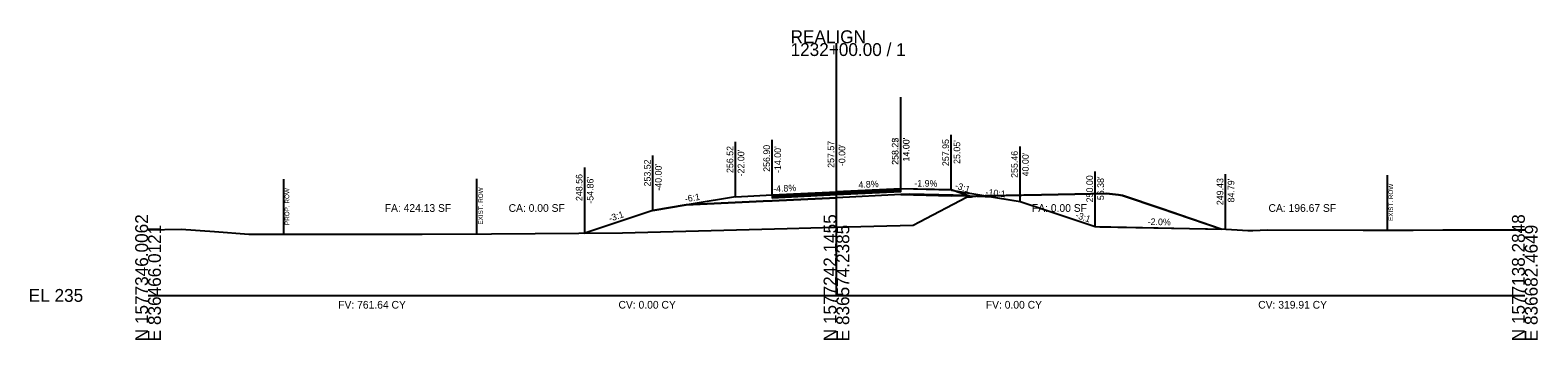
# Model space of a CAD drawing. Extents: x -26 to 6303, y -16 to 9563.
# Drawn here: x 974.3 to 1302.8, y 990.3 to 1057.8 of the extents above; entities that cross this region are included whole.
import ezdxf

# ---------------------------------------------------------------- set-up
doc = ezdxf.new("R2010")
doc.units = 0
for name, color, linetype in [('ASPHALT_19MM1', 7, 'Continuous'), ('ASPHALT_9_5MM1', 7, 'Continuous'), ('CONST_DCH', 7, 'Continuous'), ('CONST_LV3', 7, 'Continuous'), ('Draft_XS_Grid', 7, 'Continuous'), ('DTM_TEMP_DROP', 7, 'Continuous'), ('DTM_X_GROUND', 7, 'Continuous'), ('X_PROFILES_1', 7, 'Continuous'), ('X_TRANS_EOP', 7, 'Continuous'), ('XS_CELL', 7, 'Continuous'), ('XS_M_SHAPES_EARTHWORK', 7, 'Continuous'), ('XS_P_ASPHALT', 7, 'Continuous'), ('XS_P_DR_ASPHALT', 7, 'Continuous'), ('XS_P_GROUND', 7, 'Continuous'), ('XS_P_ROW', 7, 'Continuous'), ('XS_P_SHOULDER', 7, 'Continuous'), ('XS_P_SUBGRADE_GRANULAR', 7, 'Continuous'), ('XS_P_TX_CLEARZONE', 7, 'Continuous'), ('XS_P_TX_FS_BS', 7, 'Continuous'), ('XS_PLAN_CLEAR_ZONE', 7, 'Continuous'), ('XS_SHEET_EW_TX_AREA', 7, 'Continuous'), ('XS_SHEET_EW_TX_VOLUME', 7, 'Continuous'), ('XS_X_ROW', 7, 'Continuous')]:
    doc.layers.add(name, color=color, linetype=linetype)

msp = doc.modelspace()

# ---------------------------------------------------------------- linework, layer by layer
at = {"layer": 'ASPHALT_19MM1'}
msp.add_lwpolyline([(1136, 1021.57), (1136, 1021.3), (1150, 1021.97), (1150, 1021.97), (1164, 1022.64), (1164, 1022.64), (1164, 1022.91), (1164, 1022.91), (1164, 1022.91), (1150, 1022.24), (1150, 1022.24), (1136, 1021.57), (1136, 1021.57)], dxfattribs=at)
at = {"layer": 'ASPHALT_9_5MM1'}
msp.add_lwpolyline([(1136, 1021.9), (1150, 1022.57), (1150, 1022.57), (1164, 1023.25), (1164, 1023.25), (1164, 1023.12), (1164, 1023.12), (1150, 1022.45), (1150, 1022.45), (1136, 1021.78), (1136, 1021.9)], dxfattribs=at)
at = {"layer": 'CONST_LV3'}
for points in [[(1164, 1023.22), (1164, 1023.22), (1150, 1022.57)], [(1175.05, 1022.95), (1175.05, 1022.95), (1164, 1023.22)], [(1110, 1018.52), (1117.29, 1019.73), (1117.29, 1019.73)]]:
    msp.add_lwpolyline(points, dxfattribs=at)
at = {"layer": 'DTM_X_GROUND'}
msp.add_lwpolyline([(1000, 1014.33), (1007.23, 1014.43), (1014.48, 1013.91), (1021.97, 1013.35), (1029.56, 1013.34), (1059.74, 1013.36), (1074.81, 1013.44), (1103.41, 1013.61), (1139.27, 1014.61), (1149.57, 1014.88), (1166.74, 1015.34), (1168.1, 1016.05), (1178.35, 1021.4), (1180.39, 1021.66), (1180.58, 1021.69), (1181.72, 1021.71), (1194.65, 1021.96), (1201.92, 1022.09), (1208.86, 1022.23), (1211.43, 1021.9), (1212.35, 1021.79), (1220.74, 1018.95), (1233.73, 1014.49), (1239.63, 1014.17), (1240.25, 1014.13), (1240.7, 1014.15), (1243.91, 1014.27), (1264.77, 1014.21), (1275.65, 1014.25), (1282.15, 1014.27), (1283, 1014.27), (1300, 1014.29)], dxfattribs=at)
at = {"layer": 'X_TRANS_EOP'}
msp.add_line((1164, 1023.22), (1164, 1043.22), dxfattribs=at)
at = {"layer": 'XS_CELL'}
for p, q in [((1150, 1000), (1150, 1055)), ((1000, 1000), (1150, 1000)), ((1150, 1000), (1300, 1000))]:
    msp.add_line(p, q, dxfattribs=at)
at = {"layer": 'XS_M_SHAPES_EARTHWORK'}
msp.add_lwpolyline([(1095.14, 1013.56), (1103.41, 1013.61), (1139.27, 1014.61), (1149.57, 1014.88), (1166.74, 1015.34), (1168.1, 1016.05), (1178.35, 1021.4), (1179.41, 1021.53), (1178.63, 1021.79), (1166, 1022.07), (1164, 1021.97), (1150, 1021.3), (1136, 1020.63), (1134, 1020.53), (1117.29, 1019.73), (1110, 1018.52)], close=True, dxfattribs=at)
at = {"layer": 'XS_P_GROUND'}
for points in [[(1179.41, 1021.53), (1179.41, 1021.53), (1175, 1023)], [(1175.05, 1022.95), (1190, 1020.46), (1206.38, 1015)], [(1128, 1021.52), (1110, 1018.52), (1095.14, 1013.56)], [(1206.38, 1015), (1207.38, 1014.98)], [(1207.38, 1014.98), (1234.79, 1014.43)]]:
    msp.add_lwpolyline(points, dxfattribs=at)
at = {"layer": 'XS_P_ROW'}
msp.add_line((1029.56, 1013.34), (1029.56, 1025.34), dxfattribs=at)
at = {"layer": 'XS_P_SHOULDER'}
for points in [[(1128, 1021.52), (1136, 1021.9), (1136, 1021.9)], [(1175, 1023), (1164, 1023.25), (1164, 1023.25)], [(1175.05, 1022.95), (1175.05, 1022.95), (1175, 1022.95)]]:
    msp.add_lwpolyline(points, dxfattribs=at)
at = {"layer": 'XS_P_SUBGRADE_GRANULAR'}
for points in [[(1164, 1021.97), (1164, 1021.97), (1150, 1021.3)], [(1164, 1021.97), (1175, 1021.68)], [(1117.29, 1019.73), (1134, 1020.53), (1134, 1020.53), (1136, 1020.63), (1136, 1020.63)], [(1136, 1020.63), (1150, 1021.3), (1150, 1021.3)], [(1184.22, 1021.42), (1184.22, 1021.42), (1177, 1021.71), (1177, 1021.71), (1175, 1021.68)]]:
    msp.add_lwpolyline(points, dxfattribs=at)
at = {"layer": 'XS_P_TX_CLEARZONE'}
for p, q in [((1164, 1023.25), (1164, 1035.25)), ((1164, 1023.22), (1164, 1035.22)), ((1175, 1023), (1175, 1035)), ((1128, 1021.52), (1128, 1033.52)), ((1136, 1021.9), (1136, 1033.9)), ((1150, 1022.57), (1150, 1034.57)), ((1190, 1020.46), (1190, 1032.46)), ((1110, 1018.52), (1110, 1030.52)), ((1095.14, 1013.56), (1095.14, 1027.88)), ((1206.38, 1015), (1206.38, 1027)), ((1234.79, 1014.43), (1234.79, 1026.43))]:
    msp.add_line(p, q, dxfattribs=at)
at = {"layer": 'XS_P_TX_FS_BS'}
for p, q in [((1190, 1020.46), (1206.38, 1015)), ((1206.38, 1015), (1233.84, 1014.45))]:
    msp.add_line(p, q, dxfattribs=at)
for points in [[(1183.14, 1021.74), (1182.42, 1021.72), (1190, 1020.46)], [(1233.84, 1014.45), (1220.74, 1018.95), (1212.35, 1021.79), (1211.43, 1021.9), (1208.86, 1022.23), (1201.92, 1022.09), (1194.65, 1021.96), (1183.14, 1021.74)]]:
    msp.add_lwpolyline(points, dxfattribs=at)
at = {"layer": 'XS_PLAN_CLEAR_ZONE'}
msp.add_lwpolyline([(1136, 1021.78), (1136, 1021.57), (1150, 1022.24), (1150, 1022.24), (1164, 1022.91), (1164, 1022.91), (1164, 1023.12), (1164, 1023.12), (1164, 1023.12), (1150, 1022.45), (1150, 1022.45), (1136, 1021.78), (1136, 1021.78)], dxfattribs=at)
at = {"layer": 'XS_X_ROW'}
for p, q in [((1071.64, 1013.43), (1071.64, 1025.43)), ((1270.1, 1014.23), (1270.1, 1026.23))]:
    msp.add_line(p, q, dxfattribs=at)

# ---------------------------------------------------------------- texts
at = {"layer": 'CONST_DCH'}
for p in [(1135.92, 1021.78), (1149.92, 1022.45), (1163.92, 1023.13)]:
    msp.add_text('X', height=0.24, dxfattribs=at).set_placement(p)
at = {"layer": 'Draft_XS_Grid'}
msp.add_text('-', height=0.0001, dxfattribs=at).set_placement((1000, 1000))
at = {"layer": 'DTM_TEMP_DROP'}
for p in [(1174.92, 1022.83), (1179.33, 1021.41), (1095.06, 1013.44)]:
    msp.add_text('X', height=0.24, dxfattribs=at).set_placement(p)
at = {"layer": 'X_PROFILES_1'}
for p in [(1174.97, 1022.83), (1189.92, 1020.34)]:
    msp.add_text('X', height=0.24, dxfattribs=at).set_placement(p)
at = {"layer": 'XS_CELL'}
for s, p in [('1232+00.00 / 1', (1140, 1052.2)), ('REALIGN', (1140, 1055)), ('EL 235', (974, 998.6))]:
    msp.add_text(s, height=2.8, dxfattribs=at).set_placement(p)
for s, p in [('N 1577346.0062', (1000, 990)), ('E 836466.0121', (1002.8, 990)), ('N 1577242.1455', (1150, 990)), ('E 836574.2385', (1152.8, 990)), ('N 1577138.2848', (1300, 990)), ('E 836682.4649', (1302.8, 990))]:
    msp.add_text(s, height=2.8, rotation=90, dxfattribs=at).set_placement(p)
at = {"layer": 'XS_P_ASPHALT'}
msp.add_text('X', height=0.24, dxfattribs=at).set_placement((1206.3, 1014.88))
at = {"layer": 'XS_P_DR_ASPHALT'}
msp.add_text('X', height=0.24, dxfattribs=at).set_placement((1109.92, 1018.4))
at = {"layer": 'XS_P_ROW'}
msp.add_text('PROP. ROW', height=1, rotation=90, dxfattribs=at).set_placement((1030.77, 1015.34))
at = {"layer": 'XS_P_SHOULDER'}
for p in [(1174.92, 1022.88), (1127.92, 1021.4)]:
    msp.add_text('X', height=0.24, dxfattribs=at).set_placement(p)
at = {"layer": 'XS_P_SUBGRADE_GRANULAR'}
for p in [(1179.33, 1021.41), (1095.06, 1013.44), (1234.71, 1014.31)]:
    msp.add_text('X', height=0.24, dxfattribs=at).set_placement(p)
at = {"layer": 'XS_P_TX_CLEARZONE'}
for s, p in [('256.52', (1127.52, 1026.69)), ("-22.00'", (1129.92, 1025.95)), ('256.90', (1135.52, 1026.95)), ("-14.00'", (1137.92, 1026.69)), ('257.57', (1149.52, 1027.82)), ("-0.00'", (1151.92, 1028.18)), ('258.25', (1163.52, 1028.49)), ('258.22', (1163.52, 1028.46)), ("14.00'", (1165.92, 1029.22)), ("14.00'", (1165.92, 1029.19)), ('257.95', (1174.52, 1028.2)), ("25.05'", (1176.97, 1028.67)), ('253.52', (1109.52, 1023.76)), ("-40.00'", (1111.92, 1022.83)), ('255.46', (1189.52, 1025.63)), ("40.00'", (1191.92, 1025.96)), ('248.56', (1094.66, 1020.58)), ("-54.86'", (1097.06, 1020)), ('250.00', (1205.9, 1020.3)), ("56.38'", (1208.3, 1020.77)), ('249.43', (1234.31, 1019.68)), ("84.79'", (1236.71, 1020.27))]:
    msp.add_text(s, height=1.44, rotation=90, dxfattribs=at).set_placement(p)
at = {"layer": 'XS_P_TX_FS_BS'}
for s, rotation, p in [('4.8%', 2.7481, (1154.83, 1023.41)), ('-1.9%', 358.8967, (1166.96, 1023.76)), ('-6:1', 9.4642, (1117.08, 1020.3)), ('-4.8%', 2.7481, (1136.24, 1022.51)), ('-3:1', 341.968, (1175.69, 1023.38)), ('-10:1', 354.2125, (1182.44, 1021.83)), ('-3:1', 18.4332, (1100.66, 1016.04)), ('-3:1', 341.5651, (1201.96, 1016.93)), ('-2.0%', 358.8542, (1217.81, 1015.37))]:
    msp.add_text(s, height=1.44, rotation=rotation, dxfattribs=at).set_placement(p)
at = {"layer": 'XS_SHEET_EW_TX_AREA'}
for s, p in [('FA: 424.13 SF', (1051.57, 1018.22)), ('CA: 0.00 SF', (1078.57, 1018.22)), ('FA: 0.00 SF', (1192.6, 1018.22)), ('CA: 196.67 SF', (1244.15, 1018.22))]:
    msp.add_text(s, height=1.68, dxfattribs=at).set_placement(p)
at = {"layer": 'XS_SHEET_EW_TX_VOLUME'}
for s, p in [('FV: 761.64 CY', (1041.44, 997.12)), ('CV: 0.00 CY', (1102.51, 997.12)), ('FV: 0.00 CY', (1182.55, 997.12)), ('CV: 319.91 CY', (1241.91, 997.12))]:
    msp.add_text(s, height=1.68, dxfattribs=at).set_placement(p)
at = {"layer": 'XS_X_ROW'}
for p in [(1072.97, 1015.43), (1271.3, 1016.23)]:
    msp.add_text('EXIST. ROW', height=1, rotation=90, dxfattribs=at).set_placement(p)

doc.saveas('drawing.dxf')
